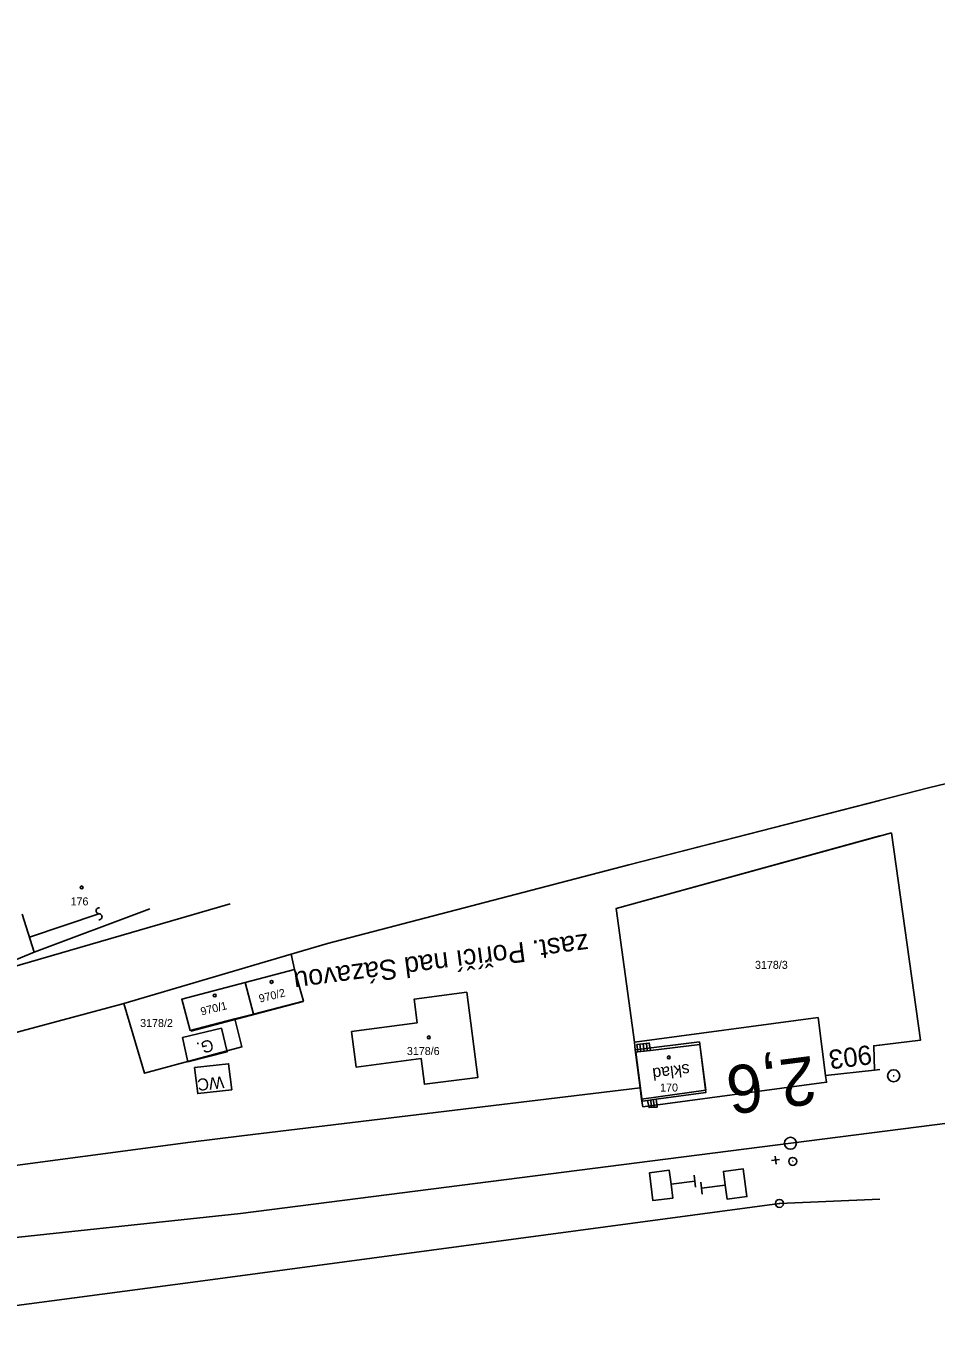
# Model space of a CAD drawing. Extents: x -728800 to -728100, y -1073200 to -1072700.
# Drawn here: x -728455.9 to -728342.2, y -1073054.1 to -1072892.3 of the extents above; entities that cross this region are included whole.
import ezdxf

# ---------------------------------------------------------------- set-up
doc = ezdxf.new("R2010")
doc.units = 0
for name, color, linetype in [('A1_OBVOD Spravy železnic', 7, 'Continuous'), ('B6_JŽM', 7, 'Continuous'), ('B7_Bodové pole', 7, 'Continuous'), ('K_01_Hranice parcel', 7, 'Continuous'), ('K_02_Parcelní čísla', 7, 'Continuous'), ('K_03_Značky druhu pozemku', 7, 'Continuous'), ('K_04_Vnitřní kresba', 7, 'Continuous'), ('K_05_Značky stavební objekty', 7, 'Continuous')]:
    doc.layers.add(name, color=color, linetype=linetype)

msp = doc.modelspace()

# ---------------------------------------------------------------- linework, layer by layer
at = {"layer": 'A1_OBVOD Spravy železnic'}
for points in [[(-728503.24, -1073052.34), (-728501.19, -1073037.94), (-728499.78, -1073032.61), (-728497.54, -1073030.15), (-728493.68, -1073027.94), (-728443.97, -1073014.59), (-728443.68, -1073014.51), (-728441.09, -1073023.23), (-728428.92, -1073019.94), (-728429.82, -1073016.43), (-728427.49, -1073015.84), (-728421.24, -1073014.23), (-728422.34, -1073010.27), (-728422.77, -1073008.34), (-728418.21, -1073007), (-728380.57, -1072997.2), (-728343.1, -1072987.57), (-728330.49, -1072984.52), (-728326.79, -1072988.95)], [(-728347.72, -1072993.16), (-728382.13, -1073002.62), (-728379.86, -1073019.33), (-728379.76, -1073020.32), (-728379.15, -1073025.03)], [(-728379.15, -1073025.03), (-728378.98, -1073026.45), (-728378.8, -1073027.41), (-728355.85, -1073024.35), (-728355.97, -1073023.5), (-728349.85, -1073022.84), (-728349.94, -1073019.8), (-728344.1, -1073019.09), (-728347.72, -1072993.16)], [(-728503.24, -1073052.34), (-728499.33, -1073052.26), (-728496.81, -1073052.21), (-728491.97, -1073053.44), (-728470.97, -1073054.08), (-728434.43, -1073049.27), (-728361.73, -1073039.5), (-728349.17, -1073038.98)]]:
    msp.add_lwpolyline(points, dxfattribs=at)
at = {"layer": 'B6_JŽM'}
for p, q in [((-728379.18, -1073019.6), (-728379.08, -1073020.53)), ((-728378.76, -1073019.55), (-728378.66, -1073020.49)), ((-728378.35, -1073019.5), (-728378.25, -1073020.44)), ((-728377.69, -1073027.49), (-728377.84, -1073026.57)), ((-728377.34, -1073027.46), (-728377.5, -1073026.52)), ((-728361.72, -1073034.02), (-728362.71, -1073034.15)), ((-728362.15, -1073034.58), (-728362.27, -1073033.59)), ((-728360.02, -1073034.23), (-728360.12, -1073034.25)), ((-728372.21, -1073037.46), (-728372.4, -1073035.97)), ((-728371.58, -1073036.86), (-728371.39, -1073038.35)), ((-728361.78, -1073039.5), (-728361.68, -1073039.5))]:
    msp.add_line(p, q, dxfattribs=at)
for points in [[(-728300.81, -1073024.35), (-728320.8, -1073026.91), (-728374.01, -1073033.72), (-728429.1, -1073040.75), (-728461.93, -1073044.27), (-728481.2, -1073044.81), (-728499.35, -1073043.65), (-728506.01, -1073042.74), (-728514.57, -1073041.33), (-728535.85, -1073036), (-728561.35, -1073026.11), (-728583.96, -1073013.52), (-728603.76, -1072998.89), (-728619.19, -1072984.42), (-728634.19, -1072966.82), (-728646.08, -1072949.19), (-728656.18, -1072930.07), (-728664.99, -1072910.23), (-728668.63, -1072901.81), (-728681.25, -1072876.02), (-728691.89, -1072859.66)], [(-728435.3, -1073017.95), (-728421.27, -1073014.25)], [(-728436.35, -1073018.78), (-728431.48, -1073017.61), (-728430.76, -1073020.54), (-728435.67, -1073021.78), (-728436.35, -1073018.78)], [(-728379.69, -1073020.59), (-728379.44, -1073020.57), (-728377.87, -1073020.4), (-728371.69, -1073019.62), (-728370.92, -1073025.62), (-728377.14, -1073026.45), (-728378.22, -1073026.64), (-728378.91, -1073026.7), (-728379.69, -1073020.59)], [(-728379.57, -1073019.64), (-728378.04, -1073019.45), (-728378, -1073019.46)], [(-728379.57, -1073019.64), (-728378, -1073019.46), (-728377.87, -1073020.4)], [(-728377.87, -1073020.4), (-728379.44, -1073020.57), (-728379.57, -1073019.64)], [(-728434.86, -1073022.51), (-728430.59, -1073022.04), (-728430.19, -1073025.28), (-728434.44, -1073025.77), (-728434.86, -1073022.51)], [(-728378.22, -1073026.64), (-728377.14, -1073026.45), (-728377.01, -1073027.44)], [(-728377.01, -1073027.44), (-728378.03, -1073027.52), (-728378.22, -1073026.64)], [(-728378.03, -1073027.52), (-728377.03, -1073027.45), (-728377.01, -1073027.44)], [(-728372.3, -1073036.71), (-728375.28, -1073037.09), (-728375.5, -1073035.36), (-728377.98, -1073035.68), (-728377.54, -1073039.15), (-728375.06, -1073038.83), (-728375.28, -1073037.09)], [(-728371.48, -1073037.61), (-728368.51, -1073037.23), (-728368.29, -1073038.96), (-728365.81, -1073038.65), (-728366.25, -1073035.18), (-728368.73, -1073035.49), (-728368.51, -1073037.23)]]:
    msp.add_lwpolyline(points, dxfattribs=at)
for centre, radius in [((-728360.36, -1073031.98), 0.75), ((-728360.07, -1073034.24), 0.5), ((-728361.73, -1073039.5), 0.499)]:
    msp.add_circle(centre, radius, dxfattribs=at)
at = {"layer": 'B7_Bodové pole'}
msp.add_line((-728347.41, -1073023.53), (-728347.51, -1073023.54), dxfattribs=at)
msp.add_circle((-728347.46, -1073023.54), 0.756, dxfattribs=at)
at = {"layer": 'K_01_Hranice parcel'}
for p, q in [((-728446.81, -1073003.3), (-728455.47, -1073006.2)), ((-728454.88, -1073008.1), (-728440.44, -1073002.68)), ((-728418.21, -1073007), (-728422.77, -1073008.34)), ((-728422.77, -1073008.34), (-728443.68, -1073014.51)), ((-728422.34, -1073010.27), (-728422.77, -1073008.34)), ((-728428.53, -1073011.87), (-728422.34, -1073010.27)), ((-728427.49, -1073015.84), (-728428.53, -1073011.87)), ((-728443.68, -1073014.51), (-728443.97, -1073014.59)), ((-728427.49, -1073015.84), (-728429.82, -1073016.43)), ((-728349.85, -1073022.84), (-728355.97, -1073023.5)), ((-728379.15, -1073025.03), (-728428.94, -1073031.04))]:
    msp.add_line(p, q, dxfattribs=at)
for points in [[(-728349.17, -1072989.13), (-728380.57, -1072997.2), (-728418.21, -1073007)], [(-728379.86, -1073019.33), (-728382.13, -1073002.62), (-728349.17, -1072993.56)], [(-728505.27, -1073017.59), (-728501.96, -1073021.14), (-728471.61, -1073014.01), (-728430.39, -1073002.04)], [(-728460.55, -1073010.42), (-728454.88, -1073008.1), (-728456.37, -1073003.35)], [(-728422.34, -1073010.27), (-728421.24, -1073014.23), (-728427.49, -1073015.84)], [(-728429.82, -1073016.43), (-728435.4, -1073017.87), (-728436.45, -1073013.98), (-728428.53, -1073011.87)], [(-728415.21, -1073018.01), (-728414.63, -1073022.47), (-728406.51, -1073021.4), (-728406.12, -1073024.61), (-728399.42, -1073023.75), (-728400.81, -1073013.1), (-728407.41, -1073013.97), (-728407.02, -1073016.93), (-728415.21, -1073018.01)], [(-728443.97, -1073014.59), (-728493.68, -1073027.94), (-728497.54, -1073030.15), (-728499.78, -1073032.61)], [(-728443.68, -1073014.51), (-728441.09, -1073023.23), (-728428.92, -1073019.94), (-728429.82, -1073016.43)], [(-728355.97, -1073023.5), (-728356.9, -1073016.27), (-728379.86, -1073019.33)], [(-728379.86, -1073019.33), (-728379.76, -1073020.32), (-728379.15, -1073025.03)], [(-728349.17, -1073019.71), (-728349.94, -1073019.8), (-728349.85, -1073022.84)], [(-728349.17, -1073022.77), (-728349.85, -1073022.84)], [(-728379.15, -1073025.03), (-728378.98, -1073026.45), (-728378.8, -1073027.41), (-728355.85, -1073024.35), (-728355.97, -1073023.5)], [(-728428.94, -1073031.04), (-728435.33, -1073031.82), (-728462.29, -1073035.43), (-728488.6, -1073038.02), (-728488.39, -1073034.38), (-728493.51, -1073034.35), (-728493.84, -1073039.37)]]:
    msp.add_lwpolyline(points, dxfattribs=at)
for centre, start, end in [((-728446.77, -1073002.92), 83.0374, 269.3345), ((-728446.78, -1073003.68), 263.0374, 89.3345)]:
    msp.add_arc(centre, 0.376, start, end, dxfattribs=at)
at = {"layer": 'K_03_Značky druhu pozemku'}
for centre in [(-728448.95, -1073000), (-728425.21, -1073011.82), (-728432.32, -1073013.52), (-728405.57, -1073018.74), (-728375.57, -1073021.24)]:
    msp.add_circle(centre, 0.175, dxfattribs=at)
at = {"layer": 'K_04_Vnitřní kresba'}
for p, q in [((-728379.76, -1073020.32), (-728371.74, -1073019.3)), ((-728371.74, -1073019.3), (-728370.95, -1073025.34)), ((-728370.95, -1073025.34), (-728378.98, -1073026.45))]:
    msp.add_line(p, q, dxfattribs=at)
at = {"layer": 'K_05_Značky stavební objekty'}
for centre in [(-728425.21, -1073011.82), (-728432.32, -1073013.52), (-728405.57, -1073018.74), (-728375.57, -1073021.24)]:
    msp.add_circle(centre, 0.175, dxfattribs=at)

# ---------------------------------------------------------------- texts
at = {"layer": 'B6_JŽM'}
for s, height, rotation, p in [('zast. Poříčí nad Sázavou', 2.5, 187.4528, (-728385.73, -1073005.76)), ('G.', 1.5, 194.1214, (-728432.68, -1073018.94)), ('2,6', 6, 187.2914, (-728357.58, -1073021.03)), ('sklad', 1.5, 187.1581, (-728373.04, -1073022.03)), ('WC', 1.5, 186.3417, (-728431.24, -1073023.58))]:
    msp.add_text(s, height=height, rotation=rotation, dxfattribs=at).set_placement(p)
at = {"layer": 'B7_Bodové pole'}
msp.add_text('903', height=2.4, rotation=187.2914, dxfattribs=at).set_placement((-728350.36, -1073019.69))
at = {"layer": 'K_02_Parcelní čísla'}
for s, p in [('176', (-728450.34, -1073002.25)), ('3178/3', (-728364.79, -1073010.18)), ('3178/2', (-728441.64, -1073017.45)), ('3178/6', (-728408.3, -1073020.95)), ('170', (-728376.65, -1073025.51))]:
    msp.add_text(s, height=1, dxfattribs=at).set_placement(p)
for s, p in [('970/2', (-728426.67, -1073014.41)), ('970/1', (-728433.95, -1073016.02))]:
    msp.add_text(s, height=1, rotation=14, dxfattribs=at).set_placement(p)

doc.saveas('drawing.dxf')
